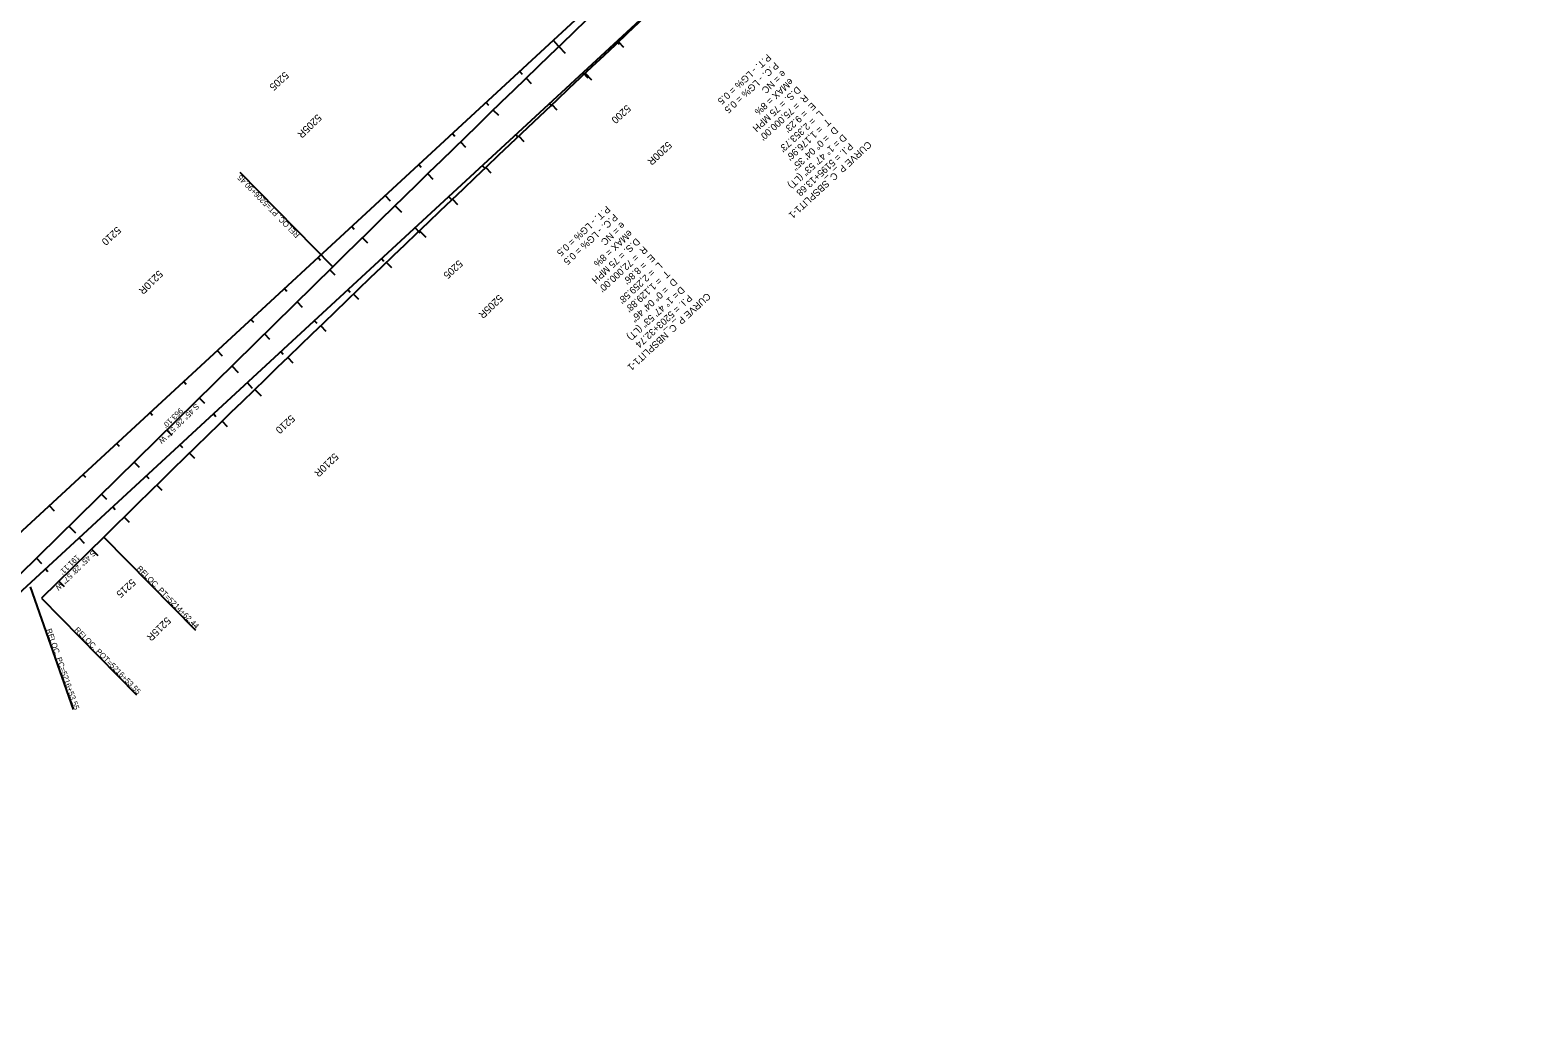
# Model space of a CAD drawing. Extents: x 2160877 to 2175861, y 601747 to 617724.
# Drawn here: x 2168975 to 2172272, y 609688 to 611869 of the extents above; entities that cross this region are included whole.
import ezdxf

# ---------------------------------------------------------------- set-up
doc = ezdxf.new("R2010")
doc.units = 0
for name, color, linetype in [('RD_HC_Cl', 7, 'Continuous'), ('RD_HC_CL_Rel', 7, 'Continuous'), ('RD_HC_Data_Rel', 7, 'Continuous'), ('RD_HC_Data_Tic', 7, 'Continuous'), ('RD_HC_Data_Tic_Rel', 7, 'Continuous'), ('RD_HC_TX_Rel_Sta50', 7, 'Continuous'), ('RD_HC_TX_Rel_StaOther', 7, 'Continuous'), ('RD_HC_TX_StaOther', 7, 'Continuous')]:
    doc.layers.add(name, color=color, linetype=linetype)

msp = doc.modelspace()

# ---------------------------------------------------------------- linework, layer by layer
at = {"layer": 'RD_HC_Cl'}
for p, q in [((2172207.3, 613775.1), (2163672.2, 605893.8)), ((2172272.5, 613704.6), (2163737.4, 605823.3))]:
    msp.add_line(p, q, dxfattribs=at)
at = {"layer": 'RD_HC_CL_Rel'}
for p, q in [((2169636.8, 611351.3), (2168950.1, 610676)), ((2169135.7, 610759.9), (2168999.4, 610625.9))]:
    msp.add_line(p, q, dxfattribs=at)
for centre, radius in [((2222221.5, 557873.6), 75000), ((2219616.9, 559421.3), 72000)]:
    msp.add_arc(centre, radius, 132.719474, 134.517591, dxfattribs=at)
at = {"layer": 'RD_HC_Data_Rel'}
for p, q in [((2169636.8, 611351.3), (2169434.4, 611557.2)), ((2169135.7, 610759.9), (2169336.4, 610555.8)), ((2168974.8, 610650.9), (2169069, 610382.3)), ((2168999.4, 610625.9), (2169207.3, 610414.5))]:
    msp.add_line(p, q, dxfattribs=at)
at = {"layer": 'RD_HC_Data_Tic'}
for p, q in [((2170118.8, 611846.6), (2170129.6, 611834.8)), ((2170257.4, 611843.9), (2170262.8, 611838)), ((2170045.3, 611778.7), (2170050.7, 611772.8)), ((2170183.9, 611776), (2170194.7, 611764.3)), ((2169971.8, 611710.9), (2169977.3, 611705)), ((2170110.4, 611708.2), (2170115.9, 611702.3)), ((2169898.4, 611643), (2169903.8, 611637.2)), ((2170037, 611640.3), (2170042.4, 611634.5)), ((2169824.9, 611575.2), (2169830.3, 611569.3)), ((2169963.5, 611572.5), (2169968.9, 611566.6)), ((2169751.4, 611507.4), (2169762.3, 611495.6)), ((2169890, 611504.7), (2169895.4, 611498.8)), ((2169678, 611439.5), (2169683.4, 611433.6)), ((2169816.5, 611436.8), (2169827.4, 611425.1)), ((2169604.5, 611371.7), (2169609.9, 611365.8)), ((2169743.1, 611369), (2169748.5, 611363.1)), ((2169531, 611303.8), (2169536.4, 611298)), ((2169669.6, 611301.1), (2169675, 611295.3)), ((2169457.5, 611236), (2169463, 611230.1)), ((2169596.1, 611233.3), (2169601.6, 611227.4)), ((2169384.1, 611168.1), (2169394.9, 611156.4)), ((2169522.7, 611165.5), (2169528.1, 611159.6)), ((2169310.6, 611100.3), (2169316, 611094.4)), ((2169449.2, 611097.6), (2169460.1, 611085.9)), ((2169237.1, 611032.5), (2169242.6, 611026.6)), ((2169375.7, 611029.8), (2169381.2, 611023.9)), ((2169163.7, 610964.6), (2169169.1, 610958.7)), ((2169302.3, 610961.9), (2169307.7, 610956.1)), ((2169090.2, 610896.8), (2169095.6, 610890.9)), ((2169228.8, 610894.1), (2169234.2, 610888.2)), ((2169016.7, 610828.9), (2169027.6, 610817.2)), ((2169155.3, 610826.3), (2169160.8, 610820.4)), ((2169081.9, 610758.4), (2169092.7, 610746.7)), ((2169008.4, 610690.6), (2169013.8, 610684.7))]:
    msp.add_line(p, q, dxfattribs=at)
at = {"layer": 'RD_HC_Data_Tic_Rel'}
for p, q in [((2170131.4, 611833.1), (2170145.3, 611818.7)), ((2170261.6, 611843.2), (2170272.5, 611831.5)), ((2170059.5, 611763.6), (2170070.6, 611752.1)), ((2170188.8, 611774.6), (2170202.5, 611760)), ((2169987.7, 611694), (2169998.8, 611682.5)), ((2170116.1, 611705.9), (2170127.1, 611694.2)), ((2169916, 611624.3), (2169927.1, 611612.8)), ((2170043.6, 611637.1), (2170054.6, 611625.5)), ((2169971.1, 611568.2), (2169982.1, 611556.6)), ((2169844.3, 611554.5), (2169855.5, 611543.1)), ((2169898.7, 611499.2), (2169909.8, 611487.6)), ((2169772.8, 611484.6), (2169786.8, 611470.3)), ((2169826.4, 611430.1), (2169840.3, 611415.6)), ((2169701.4, 611414.7), (2169712.6, 611403.2)), ((2169754.3, 611360.8), (2169765.3, 611349.3)), ((2169630, 611344.6), (2169641.2, 611333.2)), ((2169558.7, 611274.5), (2169569.9, 611263.1)), ((2169682.2, 611291.5), (2169693.3, 611280)), ((2169487.4, 611204.4), (2169498.6, 611193)), ((2169610.2, 611222.1), (2169621.3, 611210.6)), ((2169416.1, 611134.2), (2169430.1, 611120)), ((2169538.3, 611152.6), (2169549.4, 611141.1)), ((2169344.8, 611064.1), (2169356, 611052.7)), ((2169466.5, 611083), (2169480.4, 611068.7)), ((2169394.8, 611013.3), (2169405.9, 611001.9)), ((2169273.5, 610994), (2169284.7, 610982.6)), ((2169323.2, 610943.5), (2169334.3, 610932.1)), ((2169202.2, 610923.9), (2169213.4, 610912.5)), ((2169251.6, 610873.6), (2169262.8, 610862.2)), ((2169130.9, 610853.8), (2169142.1, 610842.4)), ((2169180.2, 610803.6), (2169191.4, 610792.2)), ((2169059.6, 610783.7), (2169073.6, 610769.4)), ((2169108.9, 610733.5), (2169122.9, 610719.3)), ((2168988.3, 610713.6), (2168999.5, 610702.2)), ((2169037.6, 610663.4), (2169048.8, 610652))]:
    msp.add_line(p, q, dxfattribs=at)

# ---------------------------------------------------------------- texts
at = {"layer": 'RD_HC_Data_Rel'}
for s, height, rotation, p in [('P.T. - LG% = 0.5', 15, 222.7195, (2170587.3, 611817.4)), ('P.C. - LG% = 0.5', 15, 222.7195, (2170603.6, 611799.8)), ('eMAX = 8%', 15, 222.7195, (2170636.1, 611764.5)), ('e = NC', 15, 222.7195, (2170619.8, 611782.1)), ('D.S. = 75 MPH', 15, 222.7195, (2170652.4, 611746.9)), ("R  = 75,000.00'", 15, 222.7195, (2170668.7, 611729.2)), ("L  = 2,353.73'", 15, 222.7195, (2170701.2, 611694)), ("E  = 9.23'", 15, 222.7195, (2170685, 611711.6)), ("T  = 1,176.96'", 15, 222.7195, (2170717.5, 611676.3)), ('D  = 0%%d 04\' 35"', 15, 222.7195, (2170733.8, 611658.7)), ('   = 1%%d 47\' 53" (LT)', 15, 222.7195, (2170750.1, 611641.1)), ('CURVE P_C_SBSPLIT1-1', 15, 222.7195, (2170806.9, 611627.1)), ('P.I. = 5195+13.68', 15, 222.7195, (2170766.4, 611623.4)), ('D ', 15, 222.7195, (2170752.4, 611642.1)), ('RELOC. PT=5206+90.45', 12, 134.5176, (2169565.3, 611421.2)), ('P.T. - LG% = 0.5', 15, 222.7195, (2170235.4, 611485.5)), ('P.C. - LG% = 0.5', 15, 222.7195, (2170251.7, 611467.9)), ('eMAX = 8%', 15, 222.7195, (2170284.2, 611432.6)), ('e = NC', 15, 222.7195, (2170268, 611450.2)), ('D.S. = 75 MPH', 15, 222.7195, (2170300.5, 611415)), ("R  = 72,000.00'", 15, 222.7195, (2170316.8, 611397.3)), ("L  = 2,259.58'", 15, 222.7195, (2170349.4, 611362.1)), ("E  = 8.86'", 15, 222.7195, (2170333.1, 611379.7)), ("T  = 1,129.88'", 15, 222.7195, (2170365.7, 611344.4)), ('D  = 0%%d 04\' 46"', 15, 222.7195, (2170381.9, 611326.8)), ('   = 1%%d 47\' 53" (LT)', 15, 222.7195, (2170398.2, 611309.2)), ('CURVE P_C_NBSPLIT1-1', 15, 222.7195, (2170455, 611295.2)), ('D ', 15, 222.7195, (2170398.2, 611309.2)), ('P.I. = 5203+32.74', 15, 222.7195, (2170414.5, 611291.5)), ('RELOC. PT=5214+62.44', 12, 314.5176, (2169207.2, 610690)), ('RELOC. PC=5216+53.55', 12, 289.3225, (2169009.7, 610557.2)), ('RELOC. POT=5216+53.55', 12, 314.5176, (2169071, 610556))]:
    msp.add_text(s, height=height, rotation=rotation, dxfattribs=at).set_placement(p)
at = {"layer": 'RD_HC_TX_Rel_Sta50'}
for s, rotation, p in [('5205R', 224.3721, (2169603, 611686.3)), ('5200R', 223.3538, (2170369.3, 611626.5)), ('5210R', 224.5176, (2169255.7, 611344.6)), ('5205R', 223.7517, (2169999.8, 611291.5)), ('5210R', 224.1496, (2169640, 610944.9)), ('5215R', 224.5176, (2169273.2, 610586.2))]:
    msp.add_text(s, height=16, rotation=rotation, dxfattribs=at).set_placement(p)
at = {"layer": 'RD_HC_TX_Rel_StaOther'}
for s, p in [('S 45%%d 28\' 57" W', (2169337.4, 611052.6)), ("963.10'", (2169302.1, 611043.2)), ('S 45%%d 28\' 57" W', (2169111.5, 610731.8)), ("191.11'", (2169076.2, 610722.4))]:
    msp.add_text(s, height=12, rotation=224.5176, dxfattribs=at).set_placement(p)
at = {"layer": 'RD_HC_TX_StaOther'}
for s, p in [('5205', (2169531.6, 611779.1)), ('5200', (2170279.7, 611706.6)), ('5210', (2169164.6, 611440.3)), ('5205', (2169912, 611367.1)), ('5210', (2169545, 611028.2)), ('5215', (2169196.7, 610669.6))]:
    msp.add_text(s, height=16, rotation=222.7195, dxfattribs=at).set_placement(p)

doc.saveas('drawing.dxf')
